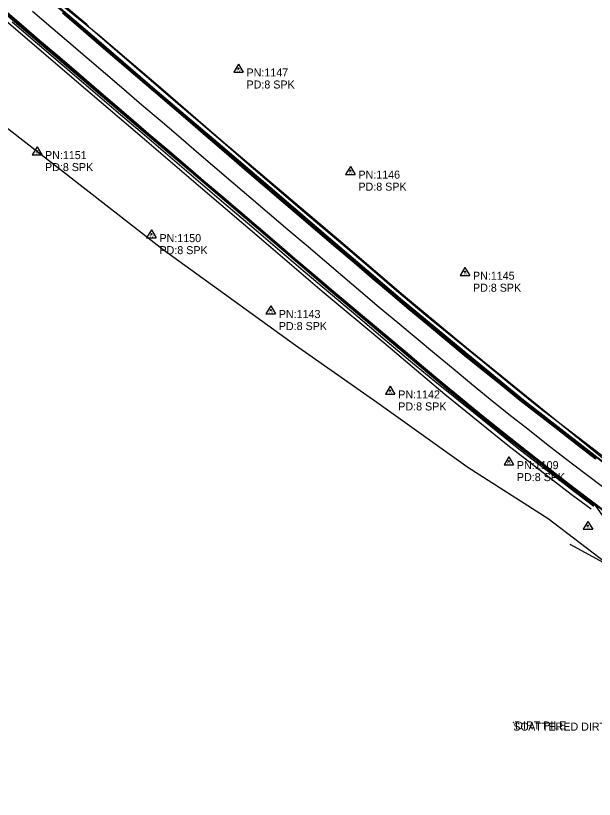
# Model space of a CAD drawing. Extents: x 878399 to 889864, y 1564003 to 1567413.
# Drawn here: x 884917.5 to 885279, y 1564850.4 to 1565339.8 of the extents above; entities that cross this region are included whole.
import ezdxf

# ---------------------------------------------------------------- set-up
doc = ezdxf.new("R2010")
doc.units = 0
for name, color, linetype in [('S_DITCHLINE', 7, 'Continuous'), ('S_EDGE_CONCRETE', 7, 'Continuous'), ('S_EDGE_PAVEMENT', 7, 'Continuous'), ('S_FIBER_OPTIC_CABLE', 7, 'Continuous'), ('S_MSC_PT_SYM', 7, 'Continuous'), ('S_PAVEMENT_CROWN', 7, 'Continuous'), ('S_SECONDARY_CTL', 7, 'Continuous'), ('S_SECONDARY_CTL_ANNOT', 7, 'Continuous'), ('S_SHOULDER', 7, 'Continuous'), ('S_SURVEY_TEXT_ANNOT', 7, 'Continuous'), ('S_UTL_PT_SYM', 7, 'Continuous')]:
    doc.layers.add(name, color=color, linetype=linetype)

msp = doc.modelspace()

# ---------------------------------------------------------------- linework, layer by layer
at = {"layer": 'S_DITCHLINE'}
for points in [[(885310.72, 1565044.3), (885294.14, 1565056.98), (885277.55, 1565069.67), (885260.97, 1565082.35), (885244.38, 1565095.03), (885226.71, 1565109.43), (885209.03, 1565123.82), (885191.36, 1565138.22), (885173.68, 1565152.61), (885155.49, 1565168.05), (885137.3, 1565183.48), (885119.12, 1565198.92), (885100.93, 1565214.35), (885083.52, 1565229.28), (885066.12, 1565244.2), (885048.72, 1565259.13), (885031.31, 1565274.06), (885014.49, 1565288.54), (884997.67, 1565303.02), (884980.86, 1565317.5), (884964.04, 1565331.98), (884961.88, 1565334.22), (884945.54, 1565347.97)], [(885278.58, 1565033.23), (885266.62, 1565042.41), (885254.65, 1565051.6), (885242.68, 1565060.78), (885230.71, 1565069.96), (885214.38, 1565083.15), (885198.04, 1565096.34), (885181.71, 1565109.54), (885165.38, 1565122.73), (885148.33, 1565137.19), (885131.28, 1565151.64), (885114.23, 1565166.1), (885097.18, 1565180.56), (885081.13, 1565194.22), (885065.07, 1565207.87), (885049.02, 1565221.53), (885032.96, 1565235.18), (885015.44, 1565250.2), (884997.92, 1565265.21), (884980.39, 1565280.23), (884962.87, 1565295.25), (884947.01, 1565308.78), (884931.14, 1565322.32), (884915.28, 1565335.85)], [(885324.96, 1564972.8), (885305.68, 1564986.74), (885284.83, 1564998.14), (885263.97, 1565009.54)]]:
    msp.add_lwpolyline(points, dxfattribs=at)
at = {"layer": 'S_EDGE_CONCRETE'}
for points in [[(884705.4, 1565550.04), (884723.26, 1565534.58), (884742.1, 1565518.69), (884780.16, 1565486.23), (884818.14, 1565453.73), (884855.98, 1565421.17), (884892.08, 1565390.2), (884930.32, 1565357.68), (884968.08, 1565325.3), (885005.99, 1565292.69), (885044.06, 1565260.33), (885082.07, 1565227.99), (885120, 1565195.47), (885157.99, 1565163.2), (885196.4, 1565131.24), (885234.81, 1565099.94), (885295.36, 1565052.86), (885310.26, 1565042.23)], [(884706.6, 1565551.45), (884725.44, 1565537.13), (884744.17, 1565521.12), (884782.46, 1565488.91), (884820.33, 1565456.29), (884857.4, 1565422.83), (884893.19, 1565391.5), (884931.44, 1565358.94), (884969.96, 1565327.51), (885007.93, 1565294.95), (885045.65, 1565262.19), (885083.76, 1565229.98), (885121.86, 1565197.67), (885159.74, 1565165.3), (885198.19, 1565133.4), (885236.59, 1565102.25), (885296.12, 1565053.84), (885311.12, 1565043.35)], [(884688.03, 1565529.41), (884693.66, 1565523.34), (884731.61, 1565490.8), (884767.2, 1565460.17), (884805.29, 1565427.8), (884843.47, 1565395.44), (884881.16, 1565362.62), (884918.8, 1565330.29), (884957.02, 1565297.6), (884994.98, 1565265.2), (885032.99, 1565232.77), (885071.05, 1565200.29), (885109.01, 1565167.81), (885147.48, 1565135.65), (885185.66, 1565103.41), (885224.98, 1565071.52), (885264.55, 1565040.98), (885276.98, 1565031.83)], [(884689.18, 1565530.77), (884695.4, 1565525.38), (884733.42, 1565492.91), (884769.21, 1565462.51), (884807.31, 1565430.15), (884845.29, 1565397.58), (884883.12, 1565364.93), (884920.9, 1565332.67), (884959.15, 1565300.1), (884997.09, 1565267.66), (885035.26, 1565235.41), (885073.28, 1565202.9), (885111.19, 1565170.37), (885149.63, 1565138.23), (885187.82, 1565106.01), (885227.08, 1565074.25), (885266.64, 1565043.69), (885278.89, 1565034.31)]]:
    msp.add_lwpolyline(points, dxfattribs=at)
at = {"layer": 'S_EDGE_PAVEMENT'}
for points in [[(884909.07, 1565343.93), (884920.49, 1565334.22), (884932.07, 1565324.31), (884943.46, 1565314.57), (884954.85, 1565304.82), (884966.24, 1565295.07), (884977.61, 1565285.31), (884988.96, 1565275.58), (885000.34, 1565265.82), (885000.34, 1565265.82), (885011.74, 1565256.09), (885023.14, 1565246.36), (885034.55, 1565236.63), (885045.95, 1565226.9), (885057.4, 1565217.14), (885068.8, 1565207.41), (885080.19, 1565197.68), (885080.19, 1565197.68), (885091.58, 1565187.93), (885102.97, 1565178.19), (885114.38, 1565168.48), (885125.98, 1565158.78), (885137.48, 1565149.17), (885148.98, 1565139.55), (885160.44, 1565129.89), (885171.89, 1565120.23), (885183.35, 1565110.57), (885194.93, 1565101.04), (885194.93, 1565101.04), (885194.93, 1565101.04), (885206.97, 1565091.3), (885218.63, 1565081.86), (885230.33, 1565072.48), (885242.15, 1565063.27), (885253.98, 1565054.05), (885265.81, 1565044.83), (885277.76, 1565035.77), (885289.77, 1565026.8)], [(884909.48, 1565344.22), (884920.89, 1565334.51), (884932.48, 1565324.6), (884943.87, 1565314.86), (884955.26, 1565305.11), (884966.64, 1565295.36), (884978.02, 1565285.6), (884989.36, 1565275.87), (885000.75, 1565266.12), (885000.75, 1565266.12), (885012.15, 1565256.38), (885023.55, 1565246.65), (885034.95, 1565236.92), (885046.35, 1565227.2), (885057.8, 1565217.43), (885069.2, 1565207.71), (885080.59, 1565197.97), (885080.59, 1565197.97), (885091.98, 1565188.23), (885103.37, 1565178.49), (885114.78, 1565168.78), (885126.38, 1565159.08), (885137.88, 1565149.46), (885149.37, 1565139.85), (885160.83, 1565130.19), (885172.29, 1565120.53), (885183.75, 1565110.87), (885195.32, 1565101.34), (885195.32, 1565101.34), (885195.32, 1565101.34), (885207.36, 1565091.6), (885219.02, 1565082.17), (885230.72, 1565072.78), (885242.54, 1565063.57), (885254.37, 1565054.35), (885266.2, 1565045.13), (885278.15, 1565036.08), (885290.16, 1565027.1)], [(884946.77, 1565341.58), (884958.15, 1565331.82), (884969.53, 1565322.06), (884980.92, 1565312.31), (884992.3, 1565302.56), (884992.3, 1565302.56), (885003.71, 1565292.79), (885015.07, 1565283.01), (885026.43, 1565273.23), (885037.78, 1565263.44), (885049.15, 1565253.68), (885060.54, 1565243.92), (885071.88, 1565234.2), (885071.88, 1565234.2), (885071.88, 1565234.2), (885083.27, 1565224.45), (885083.27, 1565224.45), (885094.68, 1565214.73), (885106.09, 1565205.01), (885117.49, 1565195.29), (885128.91, 1565185.58), (885140.26, 1565175.94), (885151.69, 1565166.24), (885163.16, 1565156.6), (885174.69, 1565147.01), (885186.21, 1565137.42), (885197.76, 1565127.87), (885209.41, 1565118.43), (885220.77, 1565109.22), (885232.43, 1565099.77), (885244.25, 1565090.55), (885256.09, 1565081.36), (885267.94, 1565072.17), (885279.79, 1565062.98)], [(884947.18, 1565341.87), (884958.56, 1565332.11), (884969.94, 1565322.35), (884981.32, 1565312.6), (884992.71, 1565302.85), (884992.71, 1565302.85), (885004.12, 1565293.08), (885015.48, 1565283.3), (885026.83, 1565273.52), (885038.19, 1565263.74), (885049.56, 1565253.97), (885060.94, 1565244.22), (885072.28, 1565234.49), (885072.28, 1565234.49), (885072.28, 1565234.49), (885083.67, 1565224.75), (885083.67, 1565224.75), (885095.08, 1565215.03), (885106.49, 1565205.31), (885117.89, 1565195.59), (885129.31, 1565185.88), (885140.66, 1565176.24), (885152.08, 1565166.53), (885163.56, 1565156.89), (885175.08, 1565147.31), (885186.6, 1565137.72), (885198.15, 1565128.17), (885209.8, 1565118.73), (885221.17, 1565109.52), (885232.82, 1565100.08), (885244.64, 1565090.85), (885256.49, 1565081.66), (885268.33, 1565072.47), (885280.18, 1565063.28)]]:
    msp.add_lwpolyline(points, dxfattribs=at)
at = {"layer": 'S_FIBER_OPTIC_CABLE'}
for p, q in [((885009.72, 1565193.54), (884909.8, 1565271.35)), ((885092.37, 1565133.9), (885009.72, 1565193.54)), ((885143.1, 1565098.22), (885092.37, 1565133.9)), ((885200.04, 1565057.66), (885143.1, 1565098.22)), ((885250.1, 1565025.48), (885200.04, 1565057.66)), ((885301.6, 1564986.24), (885250.1, 1565025.48))]:
    msp.add_line(p, q, dxfattribs=at)
at = {"layer": 'S_MSC_PT_SYM'}
for points in [[(885228.4, 1564898.27), (885228.4, 1564898.32), (885228.4, 1564898.27), (885228.35, 1564898.27), (885228.4, 1564898.27), (885228.4, 1564898.22), (885228.4, 1564898.27), (885228.45, 1564898.27)], [(885229.6, 1564899), (885229.6, 1564899.05), (885229.6, 1564899), (885229.55, 1564899), (885229.6, 1564899), (885229.6, 1564898.95), (885229.6, 1564899), (885229.65, 1564899)]]:
    msp.add_lwpolyline(points, dxfattribs=at)
at = {"layer": 'S_PAVEMENT_CROWN'}
msp.add_lwpolyline([(884928, 1565342.7), (884939.41, 1565332.94), (884950.81, 1565323.2), (884962.2, 1565313.46), (884973.6, 1565303.72), (884984.99, 1565293.98), (884996.38, 1565284.24), (885007.76, 1565274.49), (885019.14, 1565264.74), (885030.54, 1565254.99), (885041.93, 1565245.26), (885041.93, 1565245.26), (885053.32, 1565235.52), (885064.73, 1565225.78), (885076.14, 1565216.06), (885087.55, 1565206.35), (885098.96, 1565196.63), (885110.37, 1565186.91), (885121.79, 1565177.2), (885133.21, 1565167.47), (885144.66, 1565157.8), (885156.15, 1565148.17), (885156.15, 1565148.17), (885156.15, 1565148.17), (885167.64, 1565138.55), (885179.14, 1565128.94), (885190.72, 1565119.42), (885202.3, 1565109.89), (885213.93, 1565100.33), (885225.66, 1565091), (885237.42, 1565081.7), (885249.19, 1565072.4), (885261.04, 1565063.22), (885272.99, 1565054.15), (885284.94, 1565045.08)], dxfattribs=at)
at = {"layer": 'S_SECONDARY_CTL'}
for p, q in [((885056.72, 1565309.45), (885053.71, 1565304.5)), ((885056.72, 1565309.45), (885059.67, 1565304.5)), ((885053.71, 1565304.5), (885059.67, 1565304.5)), ((884930.86, 1565257.86), (884927.85, 1565252.91)), ((884930.86, 1565257.86), (884933.81, 1565252.91)), ((884927.85, 1565252.91), (884933.81, 1565252.91)), ((885126.62, 1565245.64), (885123.61, 1565240.69)), ((885126.62, 1565245.64), (885129.56, 1565240.69)), ((885123.61, 1565240.69), (885129.56, 1565240.69)), ((885002.34, 1565205.99), (884999.33, 1565201.04)), ((885002.34, 1565205.99), (885005.28, 1565201.04)), ((884999.33, 1565201.04), (885005.28, 1565201.04)), ((885198.19, 1565182.52), (885195.18, 1565177.56)), ((885198.19, 1565182.52), (885201.14, 1565177.56)), ((885195.18, 1565177.56), (885201.14, 1565177.56)), ((885076.89, 1565158.57), (885073.88, 1565153.61)), ((885076.89, 1565158.57), (885079.84, 1565153.61)), ((885073.88, 1565153.61), (885079.84, 1565153.61)), ((885151.52, 1565108.37), (885148.51, 1565103.42)), ((885151.52, 1565108.37), (885154.47, 1565103.42)), ((885148.51, 1565103.42), (885154.47, 1565103.42)), ((885225.62, 1565064.23), (885222.61, 1565059.27)), ((885225.62, 1565064.23), (885228.57, 1565059.27)), ((885222.61, 1565059.27), (885228.57, 1565059.27)), ((885275.02, 1565023.99), (885272.01, 1565019.04)), ((885275.02, 1565023.99), (885277.97, 1565019.04)), ((885272.01, 1565019.04), (885277.97, 1565019.04))]:
    msp.add_line(p, q, dxfattribs=at)
for centre, radius in [((885056.72, 1565306.84), 0.311), ((885056.72, 1565306.84), 0.183), ((885056.72, 1565306.84), 0.103), ((884930.86, 1565255.25), 0.311), ((884930.86, 1565255.25), 0.183), ((884930.86, 1565255.25), 0.103), ((885126.62, 1565243.03), 0.311), ((885126.62, 1565243.03), 0.183), ((885126.62, 1565243.03), 0.103), ((885002.34, 1565203.38), 0.311), ((885002.34, 1565203.38), 0.183), ((885002.34, 1565203.38), 0.103), ((885198.19, 1565179.91), 0.311), ((885198.19, 1565179.91), 0.183), ((885198.19, 1565179.91), 0.103), ((885076.89, 1565155.96), 0.311), ((885076.89, 1565155.96), 0.183), ((885076.89, 1565155.96), 0.103), ((885151.52, 1565105.76), 0.311), ((885151.52, 1565105.76), 0.183), ((885151.52, 1565105.76), 0.103), ((885225.62, 1565061.62), 0.311), ((885225.62, 1565061.62), 0.183), ((885225.62, 1565061.62), 0.103), ((885275.02, 1565021.38), 0.311), ((885275.02, 1565021.38), 0.183), ((885275.02, 1565021.38), 0.103)]:
    msp.add_circle(centre, radius, dxfattribs=at)
at = {"layer": 'S_SHOULDER'}
for points in [[(884891.75, 1565389.81), (884929.91, 1565357.22), (884967.7, 1565324.86), (885005.68, 1565292.33), (885043.8, 1565260.03), (885081.58, 1565227.41), (885119.6, 1565195.01), (885157.6, 1565162.73), (885196.01, 1565130.77), (885234.52, 1565099.56), (885295.12, 1565052.54), (885309.99, 1565041.88), (885349.92, 1565012.53), (885393.73, 1564987.91), (885434.98, 1564961), (885477.34, 1564934.42), (885519.82, 1564908.04)], [(884883.27, 1565365.1), (884921.11, 1565332.91), (884959.44, 1565300.44), (884997.33, 1565267.94), (885035.39, 1565235.57), (885073.41, 1565203.07), (885111.37, 1565170.59), (885149.81, 1565138.45), (885188.01, 1565106.23), (885227.26, 1565074.48), (885266.77, 1565043.86), (885279.08, 1565034.55), (885285.74, 1565025.23), (885293.12, 1565016.93), (885334.15, 1564986.97), (885375, 1564958.16), (885417.46, 1564929.91), (885459.52, 1564902.88), (885502.12, 1564876.69), (885545.5, 1564850.36)]]:
    msp.add_lwpolyline(points, dxfattribs=at)
at = {"layer": 'S_UTL_PT_SYM'}
for points in [[(885009.72, 1565193.54), (885009.72, 1565193.59), (885009.72, 1565193.54), (885009.67, 1565193.54), (885009.72, 1565193.54), (885009.72, 1565193.49), (885009.72, 1565193.54), (885009.77, 1565193.54)], [(885092.37, 1565133.9), (885092.37, 1565133.95), (885092.37, 1565133.9), (885092.32, 1565133.9), (885092.37, 1565133.9), (885092.37, 1565133.85), (885092.37, 1565133.9), (885092.42, 1565133.9)], [(885143.1, 1565098.22), (885143.1, 1565098.27), (885143.1, 1565098.22), (885143.05, 1565098.22), (885143.1, 1565098.22), (885143.1, 1565098.17), (885143.1, 1565098.22), (885143.15, 1565098.22)], [(885200.04, 1565057.66), (885200.04, 1565057.71), (885200.04, 1565057.66), (885199.99, 1565057.66), (885200.04, 1565057.66), (885200.04, 1565057.61), (885200.04, 1565057.66), (885200.09, 1565057.66)], [(885250.1, 1565025.48), (885250.1, 1565025.53), (885250.1, 1565025.48), (885250.05, 1565025.48), (885250.1, 1565025.48), (885250.1, 1565025.43), (885250.1, 1565025.48), (885250.15, 1565025.48)]]:
    msp.add_lwpolyline(points, dxfattribs=at)

# ---------------------------------------------------------------- texts
at = {"layer": 'S_SECONDARY_CTL'}
for p in [(885055.52, 1565304.83), (884929.66, 1565253.24), (885125.41, 1565241.02), (885001.13, 1565201.37), (885196.99, 1565177.9), (885075.68, 1565153.94), (885150.32, 1565103.75), (885224.42, 1565059.61), (885273.82, 1565019.37)]:
    msp.add_text('TV', height=1.5, rotation=360, dxfattribs=at).set_placement(p)
at = {"layer": 'S_SECONDARY_CTL_ANNOT'}
for s, p in [('PN:1147', (885061.72, 1565301.84)), ('PD:8 SPK', (885061.72, 1565294.34)), ('PN:1151', (884935.86, 1565250.25)), ('PD:8 SPK', (884935.86, 1565242.75)), ('PN:1146', (885131.62, 1565238.03)), ('PD:8 SPK', (885131.62, 1565230.53)), ('PN:1150', (885007.34, 1565198.38)), ('PD:8 SPK', (885007.34, 1565190.88)), ('PN:1145', (885203.19, 1565174.91)), ('PD:8 SPK', (885203.19, 1565167.41)), ('PN:1143', (885081.89, 1565150.96)), ('PD:8 SPK', (885081.89, 1565143.46)), ('PN:1142', (885156.52, 1565100.76)), ('PD:8 SPK', (885156.52, 1565093.26)), ('PN:1109', (885230.62, 1565056.62)), ('PD:8 SPK', (885230.62, 1565049.12))]:
    msp.add_text(s, height=5, dxfattribs=at).set_placement(p)
at = {"layer": 'S_SURVEY_TEXT_ANNOT'}
for s, p in [('SCATTERED DIRT PILE', (885228.4, 1564893.27)), ('DIRT PILE', (885229.6, 1564894))]:
    msp.add_text(s, height=5, dxfattribs=at).set_placement(p)

doc.saveas('drawing.dxf')
